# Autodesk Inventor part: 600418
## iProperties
Shininess: 60.0
Length Units: 11269
Angle Units: 11279
Time Units: 11290
Mass Units: 11283
Length Display Precision: 3
Angle Display Precision: 2
Compacted: True
Company: Pneumax S.p.A.
Part Number: 600418
Description: ADATTATORE PROLUNGATO MASCHIO G1/8 Ø4
Document SubType Name: Modellazione
Catalog Web Link: www.pneumaxspa.com
Density: 0.0
Volumn: 0.0
Area: 0.0
PropertySet Name: Model Information
Control State: 0
Master: False
Checked Out: False
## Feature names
1. Rivoluzione1 [Revolution]
2. Extrusion3
3. Circular Pattern2
4. Smusso3 [Chamfer]
5. Chamfer5
6. Smusso6 [Chamfer]
